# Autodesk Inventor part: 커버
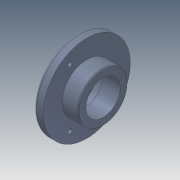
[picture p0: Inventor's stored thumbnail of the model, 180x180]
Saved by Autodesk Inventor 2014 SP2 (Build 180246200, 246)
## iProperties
Company: 한국ATC센터
Created: 2014-10
Part Number: 커버
Document SubType Name: Modeling
Designer: 한국ATC센터
Density: 2.71 g/cm^3
Material: 알루미늄 6061
Mass: 189.975 g
Surface Area: 197.126 cm^2
Volume: 70.1013 cm^3
Appearance: 슬레이트 파란색
Author: KYOUNG IL JANG
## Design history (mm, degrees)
sketch "스케치1"
  geometry: L1 (-13.5, 0)-(13.5, 0); L2 (-13.5, 0)-(-13.5, 45.5); L3 (-13.5, 45.5)-(-3.5, 45.5); L4 (-3.5, 45.5)-(-3.5, 26); L5 (-3.5, 26)-(13.5, 26); L6 (13.5, 26)-(13.5, 0); 2 further points
  constraints: 12 end point, 3 parallel, 2 perpendicular, 1 coincident, 1 horizontal, 1 midpoint
  dimensions: "d0" = 27 distance of L1.start L1.end; "d1" = 91 diameter of L3 L1; "d2" = 52 diameter of L5 L1; "d3" = 10 distance of L2.end L3.end
revolve "회전1" sketch "스케치1" stored, may be unused: angle "d4" = 90 deg
hole "구멍1" diameter "d7" = 36; stored, may be unused: countersink angle "d11" = 90 deg, drill point angle "d13" = 118 deg; dims "d5" = 10, "d6" = 10, "d8" = 6, "d9" = 40, "d10" = 8.3, "d12" = 8
sketch "스케치2"
  geometry: 2 further points
  constraints: 1 vertical alignment
  dimensions: "d14" = 35 distance of point (0, 0) point (0, 35)
hole "구멍2" sketch "스케치2" at (0, 35) diameter "d15" = 4.5; stored, may be unused: countersink angle "d19" = 90 deg, drill point angle "d21" = 118 deg; dims "d16" = 6, "d17" = 8, "d18" = 4.4, "d20" = 8
chamfer "모따기1" distance "d25" = 0.8; stored, may be unused: second distance "d26" = 2, angle "d27" = 30 deg
fillet "모깎기1" dims "d28" = 0.1, "d29" = 3
chamfer "모따기2" distance "d30" = 1; stored, may be unused: second distance "d31" = 2, angle "d32" = 30 deg
node "솔리드1"
pattern_circular "원형 패턴1" dims angle "d23" = 360 deg
